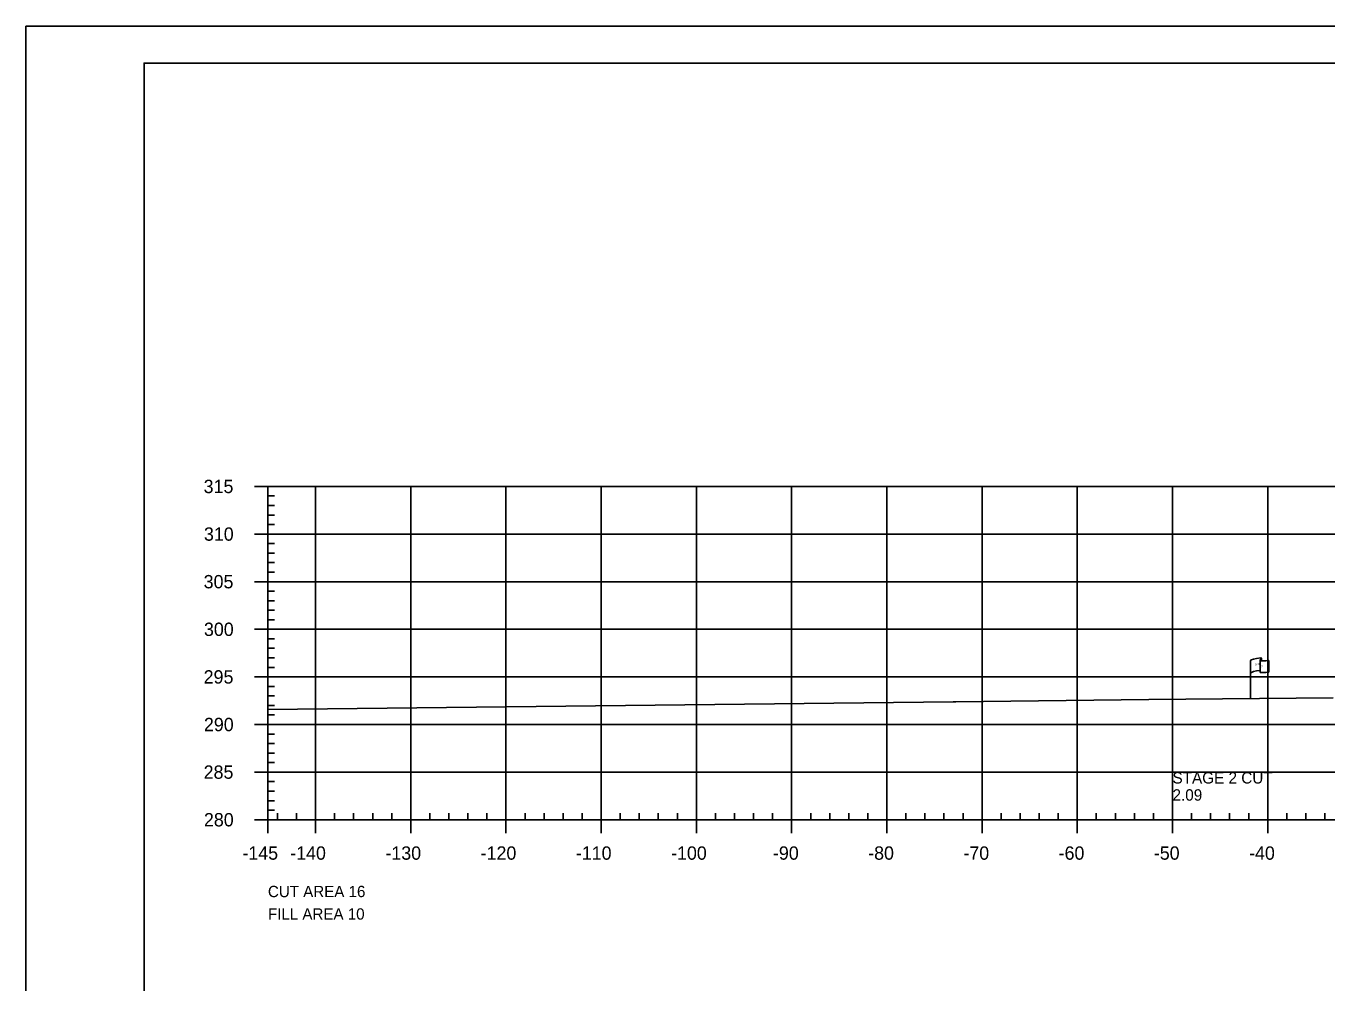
# Model space of a CAD drawing. Extents: x 1370843 to 1371177, y 380307 to 382654.
# Drawn here: x 1370843.3 to 1370979.8, y 382340.3 to 382440.8 of the extents above; entities that cross this region are included whole.
import ezdxf

# ---------------------------------------------------------------- set-up
doc = ezdxf.new("R2010")
doc.units = 0
for name, color, linetype in [('R_Axis', 7, 'Continuous'), ('R_Axis Annot', 7, 'Continuous'), ('R_Border', 7, 'Continuous'), ('R_Border Notes', 7, 'Continuous'), ('R_Exist Surface', 7, 'Continuous'), ('R_Grid', 7, 'Continuous'), ('R_No Plot', 7, 'Continuous'), ('R_ROW', 7, 'Continuous')]:
    doc.layers.add(name, color=color, linetype=linetype)

msp = doc.modelspace()

# ---------------------------------------------------------------- linework, layer by layer
at = {"layer": 'R_Axis'}
for p, q in [((1370867.31, 382392.49), (1370868.71, 382392.49)), ((1370868.71, 382357.49), (1370868.71, 382392.49)), ((1370868.71, 382391.49), (1370869.41, 382391.49)), ((1370868.71, 382390.49), (1370869.41, 382390.49)), ((1370868.71, 382389.49), (1370869.41, 382389.49)), ((1370868.71, 382388.49), (1370869.41, 382388.49)), ((1370867.31, 382387.49), (1370868.71, 382387.49)), ((1370868.71, 382386.49), (1370869.41, 382386.49)), ((1370868.71, 382385.49), (1370869.41, 382385.49)), ((1370868.71, 382384.49), (1370869.41, 382384.49)), ((1370868.71, 382383.49), (1370869.41, 382383.49)), ((1370867.31, 382382.49), (1370868.71, 382382.49)), ((1370868.71, 382381.49), (1370869.41, 382381.49)), ((1370868.71, 382380.49), (1370869.41, 382380.49)), ((1370868.71, 382379.49), (1370869.41, 382379.49)), ((1370868.71, 382378.49), (1370869.41, 382378.49)), ((1370867.31, 382377.49), (1370868.71, 382377.49)), ((1370868.71, 382376.49), (1370869.41, 382376.49)), ((1370868.71, 382375.49), (1370869.41, 382375.49)), ((1370868.71, 382374.49), (1370869.41, 382374.49)), ((1370868.71, 382373.49), (1370869.41, 382373.49)), ((1370867.31, 382372.49), (1370868.71, 382372.49)), ((1370868.71, 382371.49), (1370869.41, 382371.49)), ((1370868.71, 382370.49), (1370869.41, 382370.49)), ((1370868.71, 382369.49), (1370869.41, 382369.49)), ((1370868.71, 382368.49), (1370869.41, 382368.49)), ((1370867.31, 382367.49), (1370868.71, 382367.49)), ((1370868.71, 382366.49), (1370869.41, 382366.49)), ((1370868.71, 382365.49), (1370869.41, 382365.49)), ((1370868.71, 382364.49), (1370869.41, 382364.49)), ((1370868.71, 382363.49), (1370869.41, 382363.49)), ((1370867.31, 382362.49), (1370868.71, 382362.49)), ((1370868.71, 382361.49), (1370869.41, 382361.49)), ((1370868.71, 382360.49), (1370869.41, 382360.49)), ((1370868.71, 382359.49), (1370869.41, 382359.49)), ((1370868.71, 382358.49), (1370869.41, 382358.49)), ((1370867.31, 382357.49), (1370868.71, 382357.49)), ((1370868.71, 382357.49), (1370868.71, 382358.19)), ((1370868.71, 382357.49), (1371158.71, 382357.49)), ((1370868.71, 382356.09), (1370868.71, 382357.49)), ((1370869.71, 382357.49), (1370869.71, 382358.19)), ((1370871.71, 382357.49), (1370871.71, 382358.19)), ((1370873.71, 382356.09), (1370873.71, 382357.49)), ((1370875.71, 382357.49), (1370875.71, 382358.19)), ((1370877.71, 382357.49), (1370877.71, 382358.19)), ((1370879.71, 382357.49), (1370879.71, 382358.19)), ((1370881.71, 382357.49), (1370881.71, 382358.19)), ((1370883.71, 382356.09), (1370883.71, 382357.49)), ((1370885.71, 382357.49), (1370885.71, 382358.19)), ((1370887.71, 382357.49), (1370887.71, 382358.19)), ((1370889.71, 382357.49), (1370889.71, 382358.19)), ((1370891.71, 382357.49), (1370891.71, 382358.19)), ((1370893.71, 382356.09), (1370893.71, 382357.49)), ((1370895.71, 382357.49), (1370895.71, 382358.19)), ((1370897.71, 382357.49), (1370897.71, 382358.19)), ((1370899.71, 382357.49), (1370899.71, 382358.19)), ((1370901.71, 382357.49), (1370901.71, 382358.19)), ((1370903.71, 382356.09), (1370903.71, 382357.49)), ((1370905.71, 382357.49), (1370905.71, 382358.19)), ((1370907.71, 382357.49), (1370907.71, 382358.19)), ((1370909.71, 382357.49), (1370909.71, 382358.19)), ((1370911.71, 382357.49), (1370911.71, 382358.19)), ((1370913.71, 382356.09), (1370913.71, 382357.49)), ((1370915.71, 382357.49), (1370915.71, 382358.19)), ((1370917.71, 382357.49), (1370917.71, 382358.19)), ((1370919.71, 382357.49), (1370919.71, 382358.19)), ((1370921.71, 382357.49), (1370921.71, 382358.19)), ((1370923.71, 382356.09), (1370923.71, 382357.49)), ((1370925.71, 382357.49), (1370925.71, 382358.19)), ((1370927.71, 382357.49), (1370927.71, 382358.19)), ((1370929.71, 382357.49), (1370929.71, 382358.19)), ((1370931.71, 382357.49), (1370931.71, 382358.19)), ((1370933.71, 382356.09), (1370933.71, 382357.49)), ((1370935.71, 382357.49), (1370935.71, 382358.19)), ((1370937.71, 382357.49), (1370937.71, 382358.19)), ((1370939.71, 382357.49), (1370939.71, 382358.19)), ((1370941.71, 382357.49), (1370941.71, 382358.19)), ((1370943.71, 382356.09), (1370943.71, 382357.49)), ((1370945.71, 382357.49), (1370945.71, 382358.19)), ((1370947.71, 382357.49), (1370947.71, 382358.19)), ((1370949.71, 382357.49), (1370949.71, 382358.19)), ((1370951.71, 382357.49), (1370951.71, 382358.19)), ((1370953.71, 382356.09), (1370953.71, 382357.49)), ((1370955.71, 382357.49), (1370955.71, 382358.19)), ((1370957.71, 382357.49), (1370957.71, 382358.19)), ((1370959.71, 382357.49), (1370959.71, 382358.19)), ((1370961.71, 382357.49), (1370961.71, 382358.19)), ((1370963.71, 382356.09), (1370963.71, 382357.49)), ((1370965.71, 382357.49), (1370965.71, 382358.19)), ((1370967.71, 382357.49), (1370967.71, 382358.19)), ((1370969.71, 382357.49), (1370969.71, 382358.19)), ((1370971.71, 382357.49), (1370971.71, 382358.19)), ((1370973.71, 382356.09), (1370973.71, 382357.49)), ((1370975.71, 382357.49), (1370975.71, 382358.19)), ((1370977.71, 382357.49), (1370977.71, 382358.19)), ((1370979.71, 382357.49), (1370979.71, 382358.19))]:
    msp.add_line(p, q, dxfattribs=at)
at = {"layer": 'R_Border'}
for p, q in [((1370855.71, 382436.95), (1371171.89, 382436.95)), ((1370855.71, 382231.49), (1370855.71, 382436.95))]:
    msp.add_line(p, q, dxfattribs=at)
at = {"layer": 'R_Exist Surface'}
msp.add_line((1370940.68, 382369.88), (1370868.71, 382369.06), dxfattribs=at)
msp.add_lwpolyline([(1370940.68, 382369.88), (1370940.94, 382369.88), (1370961.24, 382370.13), (1370980.58, 382370.28)], dxfattribs=at)
at = {"layer": 'R_Grid'}
for p, q in [((1370868.71, 382392.49), (1371158.71, 382392.49)), ((1370868.71, 382357.49), (1370868.71, 382392.49)), ((1370873.71, 382357.49), (1370873.71, 382392.49)), ((1370883.71, 382357.49), (1370883.71, 382392.49)), ((1370893.71, 382357.49), (1370893.71, 382392.49)), ((1370903.71, 382357.49), (1370903.71, 382392.49)), ((1370913.71, 382357.49), (1370913.71, 382392.49)), ((1370923.71, 382357.49), (1370923.71, 382392.49)), ((1370933.71, 382357.49), (1370933.71, 382392.49)), ((1370943.71, 382357.49), (1370943.71, 382392.49)), ((1370953.71, 382357.49), (1370953.71, 382392.49)), ((1370963.71, 382357.49), (1370963.71, 382392.49)), ((1370973.71, 382357.49), (1370973.71, 382392.49)), ((1370868.71, 382387.49), (1371158.71, 382387.49)), ((1370868.71, 382382.49), (1371158.71, 382382.49)), ((1370868.71, 382377.49), (1371158.71, 382377.49)), ((1370868.71, 382372.49), (1371158.71, 382372.49)), ((1370868.71, 382367.49), (1371158.71, 382367.49)), ((1370868.71, 382362.49), (1371158.71, 382362.49)), ((1370868.71, 382357.49), (1371158.71, 382357.49))]:
    msp.add_line(p, q, dxfattribs=at)
at = {"layer": 'R_No Plot'}
msp.add_line((1370843.31, 382440.84), (1371176.64, 382440.84), dxfattribs=at)
for points in [[(1370843.3, 382440.84), (1371176.64, 382440.84), (1371176.64, 382227.51), (1370843.3, 382227.51)], [(1371089.63, 382436.95), (1371089.63, 382427.07), (1371125.36, 382427.07), (1371125.36, 382424.15), (1371148.56, 382424.15), (1371148.56, 382399.82), (1371171.89, 382399.82), (1371171.89, 382231.49), (1370855.71, 382231.49), (1370855.71, 382436.95)]]:
    msp.add_lwpolyline(points, close=True, dxfattribs=at)
at = {"layer": 'R_ROW'}
for p, q in [((1370971.91, 382370.21), (1370971.91, 382374.16)), ((1370972.91, 382374.26), (1370972.91, 382374.24)), ((1370972.91, 382374.24), (1370972.91, 382373.02)), ((1370973.07, 382374.41), (1370973.07, 382374.17)), ((1370973.84, 382374.22), (1370973.84, 382372.98))]:
    msp.add_line(p, q, dxfattribs=at)
for centre, radius, start, end in [((1370972.98, 382374.26), 0.078, 88.6458, 274.2828), ((1370972.99, 382374.41), 0.0783, 263.0712, 93.9564), ((1370972.98, 382373.02), 0.0783, 180, 273.9564)]:
    msp.add_arc(centre, radius, start, end, dxfattribs=at)
for centre, major_axis, ratio, start_param, end_param in [((1370973.49, 382374.21), (-1.58, -0.04), 0.19887, 5.030368, 6.283185), ((1370974.2, 382374.32), (-1.23, -0.13), 0.052933, 0.159456, 1.268315), ((1370973.49, 382372.89), (-1.58, -0.04), 0.19887, 5.083035, 6.194897), ((1370974.2, 382373.08), (-1.23, -0.13), 0.052933, 0.159456, 1.268315)]:
    msp.add_ellipse(centre, major_axis=major_axis, ratio=ratio, start_param=start_param, end_param=end_param, dxfattribs=at)

# ---------------------------------------------------------------- texts
at = {"layer": 'R_Axis Annot'}
for s, p in [('315', (1370861.96, 382391.79)), ('310', (1370861.99, 382386.79)), ('305', (1370861.96, 382381.79)), ('300', (1370861.99, 382376.79)), ('295', (1370861.96, 382371.79)), ('290', (1370861.99, 382366.79)), ('285', (1370861.96, 382361.79)), ('280', (1370861.99, 382356.79)), ('-145', (1370866.03, 382353.29)), ('-140', (1370871.05, 382353.29)), ('-130', (1370881.05, 382353.29)), ('-120', (1370891.05, 382353.29)), ('-110', (1370901.05, 382353.29)), ('-100', (1370911.05, 382353.29)), ('-90', (1370921.75, 382353.29)), ('-80', (1370931.75, 382353.29)), ('-70', (1370941.75, 382353.29)), ('-60', (1370951.75, 382353.29)), ('-50', (1370961.75, 382353.29)), ('-40', (1370971.75, 382353.29))]:
    msp.add_text(s, height=1.4, dxfattribs=at).set_placement(p)
at = {"layer": 'R_Border Notes'}
for s, p in [('CUT AREA 16', (1370868.71, 382349.36)), ('FILL AREA 10', (1370868.71, 382347))]:
    msp.add_text(s, height=1.1875, dxfattribs=at).set_placement(p)
at = {"layer": 'R_No Plot'}
for s, p in [('STAGE 2 CUT', (1370963.71, 382361.29)), ('2.09', (1370963.71, 382359.49))]:
    msp.add_text(s, height=1.2, dxfattribs=at).set_placement(p)
at = {"layer": 'R_ROW'}
for s, height, rotation, p in [('R ', 0.2, 9.9884, (1370972.43, 382373.67)), (' O', 0.2, 9.9884, (1370972.57, 382373.71)), ('W', 0.2, 351.1788, (1370972.9, 382373.54)), ('DWB 11-9-07', 0.001, 90, (1370973.07, 382374.17)), ('DWB 11-9-07', 0.001, 5.0717, (1370973.83, 382372.98)), ('DWB 11-9-07', 0.001, 90, (1370971.91, 382370.21))]:
    msp.add_text(s, height=height, rotation=rotation, dxfattribs=at).set_placement(p)

doc.saveas('drawing.dxf')
